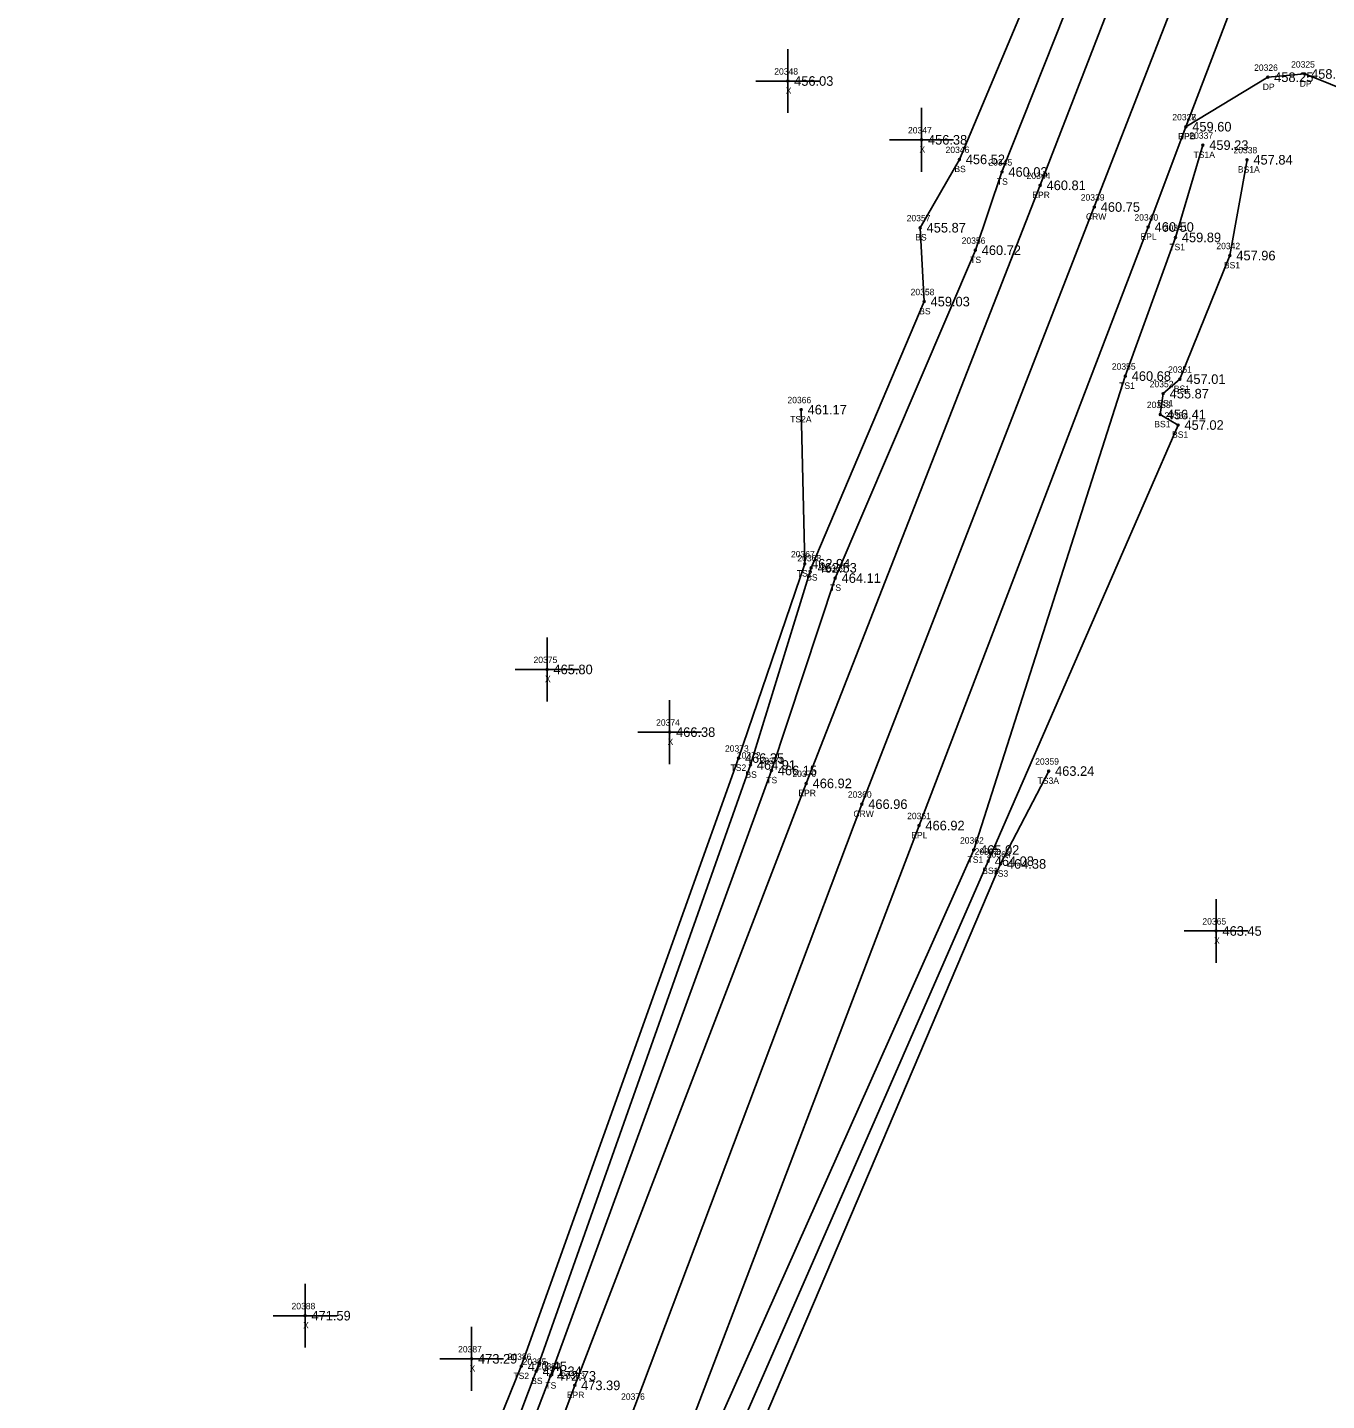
# Model space of a CAD drawing. Extents: x 1763022 to 1764007, y 824123 to 825394.
# Drawn here: x 1763166.5 to 1763369.7, y 824338.7 to 824553.5 of the extents above; entities that cross this region are included whole.
import ezdxf

# ---------------------------------------------------------------- set-up
doc = ezdxf.new("R2010")
doc.units = 0
for name, color, linetype in [('RD_DTM_BkLn1', 7, 'Continuous'), ('RD_DTM_BkLn2', 7, 'Continuous'), ('RD_DTM_BkLn_txCode', 7, 'Continuous'), ('RD_EX_Driveway', 7, 'Continuous'), ('RD_EX_Driveway_txCode', 7, 'Continuous'), ('RD_EX_Misc', 7, 'Continuous'), ('RD_EX_Misc_txCode', 7, 'Continuous'), ('RD_EX_Road', 7, 'Continuous'), ('RD_EX_Road_txCode', 7, 'Continuous'), ('RD_EX_TX_Driveway_ELEV', 7, 'Continuous'), ('RD_EX_TX_Misc_ELEV', 7, 'Continuous'), ('RD_EX_TX_Road_ELEV', 7, 'Continuous'), ('RD_HC_Survey_ELEV', 7, 'Continuous'), ('RD_HC_Survey_txCode', 7, 'Continuous'), ('RD_SMD_Locator', 7, 'Continuous')]:
    doc.layers.add(name, color=color, linetype=linetype)

msp = doc.modelspace()

# ---------------------------------------------------------------- linework, layer by layer
at = {"layer": 'RD_DTM_BkLn1'}
msp.add_lwpolyline([(1763465.6, 824795.18), (1763438.99, 824751.97), (1763414.16, 824707.73), (1763391.5, 824663.21), (1763370.27, 824618.19), (1763351.39, 824571.8), (1763333.36, 824525.39), (1763297, 824431.97), (1763261.49, 824337.79), (1763225.86, 824243.32), (1763189.96, 824148.95)], dxfattribs=at)
at = {"layer": 'RD_DTM_BkLn2'}
for points in [[(1763437.34, 824834), (1763430.66, 824820.06), (1763415.77, 824811.96), (1763415.35, 824798.51), (1763416.46, 824790.14), (1763418.19, 824781.43), (1763421.71, 824775.16), (1763417.19, 824763.87), (1763415.91, 824751.32), (1763399.06, 824714.58), (1763377.03, 824668.46), (1763355.81, 824623.79), (1763331.1, 824577.59), (1763312.25, 824532.84), (1763306.13, 824522.15), (1763306.75, 824510.59), (1763289.07, 824468.95), (1763279.57, 824438.1), (1763246.06, 824343.25), (1763209.87, 824247.25), (1763175.28, 824154.06)], [(1763453.01, 824802.49), (1763449.47, 824806.22), (1763441.02, 824809.92), (1763431.56, 824802.85), (1763425.71, 824792.63), (1763430.16, 824781.29), (1763430.95, 824776.81), (1763424.71, 824760.36), (1763418.93, 824749.28), (1763401.15, 824713.73), (1763378.81, 824667.77), (1763358.94, 824622.73), (1763337, 824576.46), (1763318.92, 824530.87), (1763314.75, 824518.63), (1763292.84, 824467.34), (1763282.85, 824437.24), (1763248.29, 824342.54), (1763211.77, 824246.85), (1763177.66, 824153.22)], [(1763350.33, 824535.07), (1763346.05, 824520.63), (1763338.21, 824498.94), (1763314.49, 824424.8), (1763273.82, 824333.54), (1763238.48, 824239.25), (1763202.86, 824142.98)], [(1763357.24, 824532.78), (1763354.57, 824517.79), (1763346.74, 824498.46), (1763344.14, 824496.19), (1763343.68, 824492.93), (1763346.46, 824491.28), (1763316.78, 824423.05), (1763276.87, 824331.84), (1763241.33, 824237.75), (1763205.15, 824141.91)], [(1763287.52, 824493.69), (1763288.06, 824469.58), (1763277.71, 824439.18), (1763243.74, 824344.03), (1763205.31, 824249.12), (1763166.5, 824157.97)], [(1763326.22, 824437.15), (1763318.69, 824422.62), (1763279.62, 824330.81), (1763248.03, 824236.33), (1763218.78, 824139.42)]]:
    msp.add_lwpolyline(points, dxfattribs=at)
at = {"layer": 'RD_EX_Driveway'}
msp.add_lwpolyline([(1763364.49, 824579.4), (1763367.96, 824574.32), (1763373.63, 824569.51), (1763385.75, 824564.13), (1763378.09, 824541.5), (1763366.26, 824546.2), (1763360.49, 824545.69), (1763347.68, 824537.95)], dxfattribs=at)
at = {"layer": 'RD_EX_Misc'}
for p, q in [((1763285.41, 824540.1), (1763285.41, 824550.1)), ((1763280.41, 824545.1), (1763290.41, 824545.1)), ((1763306.34, 824530.9), (1763306.34, 824540.9)), ((1763301.34, 824535.9), (1763311.34, 824535.9)), ((1763247.77, 824448.05), (1763247.77, 824458.05)), ((1763242.77, 824453.05), (1763252.77, 824453.05)), ((1763266.94, 824438.24), (1763266.94, 824448.24)), ((1763261.94, 824443.24), (1763271.94, 824443.24)), ((1763352.4, 824407.13), (1763352.4, 824417.13)), ((1763347.4, 824412.13), (1763357.4, 824412.13)), ((1763209.92, 824346.95), (1763209.92, 824356.95)), ((1763204.92, 824351.95), (1763214.92, 824351.95)), ((1763235.97, 824340.2), (1763235.97, 824350.2)), ((1763230.97, 824345.2), (1763240.97, 824345.2))]:
    msp.add_line(p, q, dxfattribs=at)
at = {"layer": 'RD_EX_Road'}
for points in [[(1763458.16, 824800.38), (1763431, 824756.75), (1763406.01, 824711.9), (1763384.24, 824666.74), (1763362.81, 824620.84), (1763342.79, 824575), (1763324.89, 824528.78), (1763288.3, 824435.22), (1763252.09, 824341.05), (1763216.31, 824245.88), (1763180.37, 824152.33)], [(1763474.08, 824789.56), (1763447.08, 824747.55), (1763422.65, 824703.33), (1763399.6, 824659.26), (1763379.31, 824614.36), (1763364.49, 824579.4), (1763364.49, 824579.4), (1763359.36, 824568.52), (1763347.68, 824537.95), (1763341.79, 824522.26), (1763305.94, 824428.62), (1763270.17, 824334.76), (1763235.03, 824239.84), (1763198.43, 824144.73)]]:
    msp.add_lwpolyline(points, dxfattribs=at)
at = {"layer": 'RD_SMD_Locator'}
for centre in [(1763366.26, 824546.2), (1763285.41, 824545.1), (1763360.49, 824545.69), (1763347.68, 824537.95), (1763347.68, 824537.95), (1763306.34, 824535.9), (1763350.33, 824535.07), (1763312.25, 824532.84), (1763318.92, 824530.87), (1763357.24, 824532.78), (1763324.89, 824528.78), (1763333.36, 824525.39), (1763341.79, 824522.26), (1763306.13, 824522.15), (1763346.05, 824520.63), (1763314.75, 824518.63), (1763354.57, 824517.79), (1763306.75, 824510.59), (1763338.21, 824498.94), (1763346.74, 824498.46), (1763344.14, 824496.19), (1763287.52, 824493.69), (1763343.68, 824492.93), (1763346.46, 824491.28), (1763288.06, 824469.58), (1763289.07, 824468.95), (1763292.84, 824467.34), (1763247.77, 824453.05), (1763266.94, 824443.24), (1763277.71, 824439.18), (1763279.57, 824438.1), (1763282.85, 824437.24), (1763326.22, 824437.15), (1763288.3, 824435.22), (1763297, 824431.97), (1763305.94, 824428.62), (1763314.49, 824424.8), (1763316.78, 824423.05), (1763318.69, 824422.62), (1763352.4, 824412.13), (1763209.92, 824351.95), (1763235.97, 824345.2), (1763243.74, 824344.03), (1763246.06, 824343.25), (1763248.29, 824342.54), (1763252.09, 824341.05)]:
    msp.add_circle(centre, 0.15, dxfattribs=at)

# ---------------------------------------------------------------- texts
at = {"layer": 'RD_DTM_BkLn_txCode'}
for s, p in [('20337', (1763348.22, 824536.07)), ('20346', (1763310.1, 824533.84)), ('TS1A', (1763348.88, 824533.07)), ('20338', (1763355.12, 824533.78)), ('BS', (1763311.47, 824530.84)), ('20345', (1763316.8, 824531.87)), ('BS1A', (1763355.81, 824530.78)), ('TS', (1763318.12, 824528.87)), ('20357', (1763304.01, 824523.15)), ('20341', (1763344.22, 824521.63)), ('BS', (1763305.35, 824520.15)), ('20356', (1763312.61, 824519.63)), ('TS1', (1763345.09, 824518.63)), ('20342', (1763352.45, 824518.79)), ('TS', (1763313.95, 824516.63)), ('BS1', (1763353.63, 824515.79)), ('20358', (1763304.63, 824511.59)), ('BS', (1763305.97, 824508.59)), ('20355', (1763336.1, 824499.94)), ('20351', (1763344.9, 824499.46)), ('TS1', (1763337.25, 824496.94)), ('20352', (1763342.02, 824497.19)), ('BS1', (1763345.79, 824496.46)), ('20366', (1763285.36, 824494.69)), ('20353', (1763341.57, 824493.93)), ('BS1', (1763343.2, 824494.19)), ('TS2A', (1763285.79, 824491.69)), ('20354', (1763344.34, 824492.28)), ('BS1', (1763342.74, 824490.93)), ('BS1', (1763345.52, 824489.28)), ('20367', (1763285.92, 824470.58)), ('20368', (1763286.92, 824469.95)), ('20369', (1763290.7, 824468.34)), ('TS2', (1763286.82, 824467.58)), ('BS', (1763288.29, 824466.95)), ('TS', (1763292.04, 824465.34)), ('20373', (1763275.59, 824440.18)), ('20372', (1763277.45, 824439.1)), ('20371', (1763281.01, 824438.24)), ('20359', (1763324.11, 824438.15)), ('TS2', (1763276.46, 824437.18)), ('BS', (1763278.79, 824436.1)), ('TS', (1763282.05, 824435.24)), ('TS3A', (1763324.49, 824435.15)), ('20362', (1763312.35, 824425.8)), ('TS1', (1763313.53, 824422.8)), ('20363', (1763314.64, 824424.05)), ('20364', (1763316.55, 824423.62)), ('BS1', (1763315.83, 824421.05)), ('TS3', (1763317.44, 824420.62)), ('20386', (1763241.6, 824345.03)), ('20385', (1763243.95, 824344.25)), ('20384', (1763246.18, 824343.54)), ('TS2', (1763242.5, 824342.03)), ('BS', (1763245.28, 824341.25)), ('TS', (1763247.5, 824340.54))]:
    msp.add_text(s, height=1, dxfattribs=at).set_placement(p)
at = {"layer": 'RD_EX_Driveway_txCode'}
for s, p in [('20325', (1763364.14, 824547.2)), ('20326', (1763358.35, 824546.69)), ('DP', (1763359.71, 824543.69)), ('DP', (1763365.48, 824544.2)), ('20327', (1763345.56, 824538.95)), ('DPB', (1763346.43, 824535.95))]:
    msp.add_text(s, height=1, dxfattribs=at).set_placement(p)
at = {"layer": 'RD_EX_Misc_txCode'}
for s, p in [('20348', (1763283.3, 824546.1)), ('X', (1763285.1, 824543.1)), ('20347', (1763304.22, 824536.9)), ('X', (1763306.02, 824533.9)), ('20375', (1763245.65, 824454.05)), ('X', (1763247.45, 824451.05)), ('20374', (1763264.82, 824444.24)), ('X', (1763266.62, 824441.24)), ('20365', (1763350.26, 824413.13)), ('X', (1763352.09, 824410.13)), ('20388', (1763207.8, 824352.95)), ('X', (1763209.61, 824349.95)), ('20387', (1763233.85, 824346.2)), ('X', (1763235.65, 824343.2))]:
    msp.add_text(s, height=1, dxfattribs=at).set_placement(p)
at = {"layer": 'RD_EX_Road_txCode'}
for s, p in [('20328', (1763345.56, 824538.95)), ('EPL', (1763346.47, 824535.95)), ('20344', (1763322.77, 824529.78)), ('EPR', (1763323.66, 824526.78)), ('20340', (1763339.63, 824523.26)), ('EPL', (1763340.59, 824520.26)), ('20370', (1763286.14, 824436.22)), ('EPR', (1763287.07, 824433.22)), ('20361', (1763304.08, 824429.62)), ('EPL', (1763304.73, 824426.62)), ('20383', (1763249.97, 824342.05)), ('EPR', (1763250.86, 824339.05))]:
    msp.add_text(s, height=1, dxfattribs=at).set_placement(p)
at = {"layer": 'RD_EX_TX_Driveway_ELEV'}
for s, p in [('458.25', (1763361.49, 824544.94)), ('458.02', (1763367.26, 824545.45)), ('459.60', (1763348.68, 824537.2))]:
    msp.add_text(s, height=1.5, dxfattribs=at).set_placement(p)
at = {"layer": 'RD_EX_TX_Misc_ELEV'}
for s, p in [('456.03', (1763286.41, 824544.35)), ('456.38', (1763307.34, 824535.15)), ('459.23', (1763351.33, 824534.32)), ('456.52', (1763313.25, 824532.09)), ('457.84', (1763358.24, 824532.03)), ('460.03', (1763319.92, 824530.12)), ('455.87', (1763307.13, 824521.4)), ('459.89', (1763347.05, 824519.88)), ('460.72', (1763315.75, 824517.88)), ('457.96', (1763355.57, 824517.04)), ('459.03', (1763307.75, 824509.84)), ('460.68', (1763339.21, 824498.19)), ('457.01', (1763347.74, 824497.71)), ('455.87', (1763345.14, 824495.44)), ('461.17', (1763288.52, 824492.94)), ('456.41', (1763344.68, 824492.18)), ('457.02', (1763347.46, 824490.53)), ('462.94', (1763289.06, 824468.83)), ('462.53', (1763290.07, 824468.2)), ('464.11', (1763293.84, 824466.59)), ('465.80', (1763248.77, 824452.3)), ('466.38', (1763267.94, 824442.49)), ('466.35', (1763278.71, 824438.43)), ('464.91', (1763280.57, 824437.35)), ('466.15', (1763283.85, 824436.49)), ('463.24', (1763327.22, 824436.4)), ('465.02', (1763315.49, 824424.05)), ('464.08', (1763317.78, 824422.3)), ('464.38', (1763319.69, 824421.87)), ('463.45', (1763353.4, 824411.38)), ('471.59', (1763210.92, 824351.2)), ('473.29', (1763236.97, 824344.45)), ('473.45', (1763244.74, 824343.28)), ('471.34', (1763247.06, 824342.5)), ('472.73', (1763249.29, 824341.79))]:
    msp.add_text(s, height=1.5, dxfattribs=at).set_placement(p)
at = {"layer": 'RD_EX_TX_Road_ELEV'}
for s, p in [('459.60', (1763348.68, 824537.2)), ('460.81', (1763325.89, 824528.03)), ('460.50', (1763342.79, 824521.51)), ('466.92', (1763289.3, 824434.47)), ('466.92', (1763306.94, 824427.87)), ('473.39', (1763253.09, 824340.3))]:
    msp.add_text(s, height=1.5, dxfattribs=at).set_placement(p)
at = {"layer": 'RD_HC_Survey_ELEV'}
for s, p in [('460.75', (1763334.36, 824524.64)), ('466.96', (1763298, 824431.22))]:
    msp.add_text(s, height=1.5, dxfattribs=at).set_placement(p)
at = {"layer": 'RD_HC_Survey_txCode'}
for s, p in [('20339', (1763331.24, 824526.39)), ('CRW', (1763332.05, 824523.39)), ('20360', (1763294.81, 824432.97)), ('CRW', (1763295.68, 824429.97)), ('20376', (1763259.34, 824338.79))]:
    msp.add_text(s, height=1, dxfattribs=at).set_placement(p)

doc.saveas('drawing.dxf')
